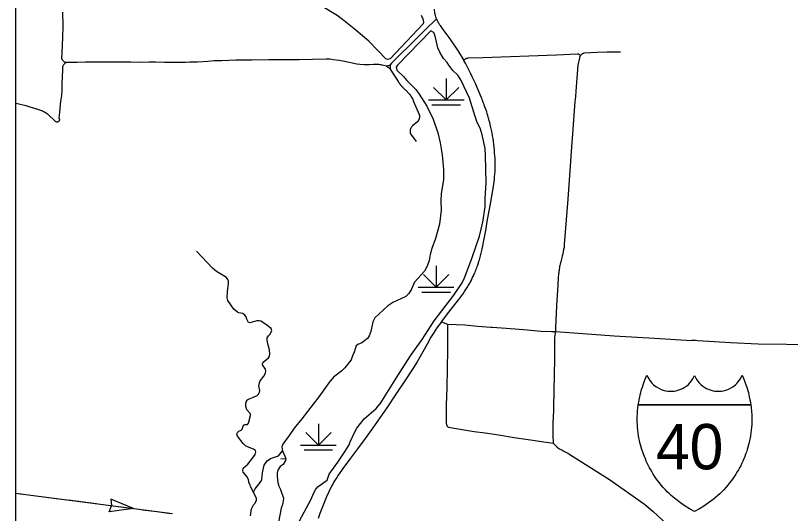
# Model space of a CAD drawing. Extents: x 1127717 to 1741049, y 2026793 to 2244711.
# Drawn here: x 1278363 to 1289221, y 2084628 to 2091610 of the extents above; entities that cross this region are included whole.
import ezdxf

# ---------------------------------------------------------------- set-up
doc = ezdxf.new("R2010")
doc.units = 0
for name, color, linetype in [('1', 7, 'Continuous'), ('23', 7, 'Continuous'), ('31', 7, 'Continuous'), ('32', 7, 'Continuous'), ('35', 7, 'Continuous'), ('43', 7, 'Continuous'), ('44', 7, 'Continuous'), ('45', 7, 'Continuous'), ('47', 7, 'Continuous')]:
    doc.layers.add(name, color=color, linetype=linetype)

msp = doc.modelspace()

# ---------------------------------------------------------------- linework, layer by layer
at = {"layer": '1'}
msp.add_lwpolyline([(1349634, 2111942), (1278363, 2111942), (1278363, 2066677), (1349634, 2066677)], close=True, dxfattribs=at)
at = {"layer": '23'}
for points in [[(1287088, 2086152), (1287094, 2086189), (1287100, 2086223), (1287109, 2086266), (1287115, 2086294), (1287123, 2086327), (1287134, 2086366), (1287145, 2086399), (1287156, 2086432), (1287171, 2086474), (1287186, 2086512), (1287199, 2086543), (1287210, 2086566), (1287222, 2086541), (1287235, 2086516), (1287250, 2086494), (1287269, 2086469), (1287284, 2086452), (1287303, 2086434), (1287322, 2086418), (1287342, 2086403), (1287375, 2086384), (1287409, 2086368), (1287439, 2086357), (1287469, 2086350), (1287501, 2086344), (1287539, 2086342), (1287563, 2086342), (1287591, 2086345), (1287617, 2086349), (1287644, 2086356), (1287671, 2086365), (1287707, 2086381), (1287732, 2086395), (1287762, 2086415), (1287790, 2086439), (1287810, 2086459), (1287833, 2086488), (1287853, 2086516), (1287864, 2086537), (1287876, 2086563)], [(1287876, 2086563), (1287889, 2086537), (1287900, 2086516), (1287920, 2086488), (1287943, 2086459), (1287963, 2086439), (1287991, 2086415), (1288021, 2086395), (1288046, 2086381), (1288082, 2086365), (1288109, 2086356), (1288136, 2086349), (1288161, 2086345), (1288190, 2086342), (1288214, 2086342), (1288252, 2086344), (1288284, 2086350), (1288314, 2086357), (1288344, 2086368), (1288378, 2086384), (1288411, 2086403), (1288431, 2086418), (1288450, 2086434), (1288469, 2086452), (1288484, 2086469), (1288503, 2086494), (1288518, 2086516), (1288531, 2086541), (1288543, 2086566), (1288554, 2086543), (1288567, 2086512), (1288582, 2086474), (1288597, 2086432), (1288608, 2086399), (1288619, 2086366), (1288630, 2086327), (1288638, 2086294), (1288644, 2086266), (1288653, 2086223), (1288659, 2086189), (1288665, 2086152)], [(1287876, 2084658), (1287807, 2084695), (1287747, 2084731), (1287680, 2084776), (1287617, 2084824), (1287549, 2084882), (1287524, 2084906), (1287495, 2084934), (1287468, 2084962), (1287438, 2084994), (1287410, 2085027), (1287385, 2085057), (1287359, 2085091), (1287336, 2085124), (1287315, 2085154), (1287297, 2085182), (1287282, 2085206), (1287262, 2085240), (1287247, 2085267), (1287230, 2085299), (1287214, 2085333), (1287200, 2085363), (1287187, 2085393), (1287173, 2085427), (1287161, 2085458), (1287150, 2085490), (1287139, 2085524), (1287128, 2085558), (1287119, 2085591), (1287112, 2085623), (1287105, 2085650), (1287101, 2085671), (1287093, 2085711), (1287086, 2085758), (1287081, 2085796), (1287078, 2085837), (1287076, 2085870), (1287074, 2085912), (1287074, 2085951), (1287074, 2085994), (1287076, 2086023), (1287077, 2086049), (1287078, 2086065), (1287083, 2086108), (1287088, 2086152)], [(1288665, 2086152), (1287088, 2086152)], [(1287088, 2086152), (1288665, 2086152)], [(1288665, 2086152), (1288670, 2086108), (1288675, 2086065), (1288676, 2086049), (1288677, 2086023), (1288679, 2085994), (1288679, 2085951), (1288679, 2085912), (1288677, 2085870), (1288675, 2085837), (1288672, 2085796), (1288667, 2085758), (1288660, 2085711), (1288652, 2085671), (1288648, 2085650), (1288641, 2085623), (1288634, 2085591), (1288625, 2085558), (1288614, 2085524), (1288603, 2085490), (1288592, 2085458), (1288580, 2085427), (1288566, 2085393), (1288553, 2085363), (1288539, 2085333), (1288523, 2085299), (1288506, 2085267), (1288491, 2085240), (1288471, 2085206), (1288456, 2085182), (1288438, 2085154), (1288417, 2085124), (1288394, 2085091), (1288368, 2085057), (1288343, 2085027), (1288315, 2084994), (1288285, 2084962), (1288258, 2084934), (1288229, 2084906), (1288204, 2084882), (1288136, 2084824), (1288073, 2084776), (1288006, 2084731), (1287946, 2084695), (1287876, 2084658)]]:
    msp.add_lwpolyline(points, dxfattribs=at)
at = {"layer": '31'}
for points in [[(1284263, 2091560), (1284257, 2091576), (1284252, 2091593), (1284247, 2091611), (1284243, 2091628), (1284239, 2091645), (1284236, 2091663), (1284234, 2091681), (1284233, 2091699)], [(1284263, 2091560), (1284250, 2091552), (1284213, 2091519), (1284146, 2091453), (1283929, 2091235), (1283705, 2091016), (1283630, 2090941), (1283613, 2090917)], [(1284263, 2091560), (1284264, 2091557), (1284267, 2091550), (1284268, 2091548), (1284271, 2091541), (1284272, 2091540), (1284275, 2091533), (1284276, 2091531), (1284279, 2091524), (1284280, 2091523), (1284284, 2091516), (1284284, 2091514), (1284288, 2091508), (1284289, 2091506), (1284293, 2091500), (1284294, 2091498), (1284298, 2091492), (1284299, 2091490), (1284303, 2091484), (1284304, 2091482), (1284308, 2091476), (1284309, 2091474), (1284313, 2091468), (1284350, 2091416), (1284432, 2091303), (1284459, 2091268), (1284563, 2091109), (1284644, 2090977)], [(1284929, 2090359), (1284929, 2090361), (1284921, 2090381), (1284921, 2090383), (1284912, 2090405), (1284911, 2090407), (1284903, 2090429), (1284902, 2090431), (1284901, 2090435), (1284900, 2090436), (1284892, 2090457), (1284891, 2090458), (1284833, 2090599), (1284812, 2090647), (1284790, 2090696), (1284767, 2090743), (1284744, 2090791), (1284719, 2090838), (1284695, 2090885), (1284670, 2090931), (1284644, 2090977)], [(1283613, 2090917), (1283605, 2090913), (1283596, 2090909), (1283588, 2090906), (1283579, 2090903), (1283570, 2090900), (1283561, 2090898)], [(1283561, 2090898), (1283571, 2090892), (1283580, 2090886), (1283589, 2090879), (1283598, 2090872), (1283606, 2090865), (1283614, 2090857)], [(1283613, 2090917), (1283611, 2090907), (1283610, 2090897), (1283610, 2090887), (1283611, 2090877), (1283612, 2090867), (1283614, 2090857)], [(1283614, 2090857), (1283724, 2090683), (1283725, 2090681), (1283729, 2090675), (1283730, 2090673), (1283736, 2090665), (1283738, 2090664), (1283743, 2090656), (1283745, 2090654), (1283751, 2090646), (1283752, 2090645), (1283758, 2090637), (1283759, 2090635), (1283766, 2090628), (1283767, 2090626), (1283774, 2090619), (1283775, 2090617), (1283782, 2090610), (1283783, 2090608), (1283790, 2090601), (1283791, 2090600), (1283798, 2090592), (1283799, 2090591), (1283806, 2090584), (1283808, 2090583), (1283815, 2090576), (1283816, 2090574), (1283824, 2090568), (1283825, 2090566), (1283883, 2090506), (1283895, 2090489), (1283906, 2090472), (1283917, 2090454), (1283929, 2090436), (1283941, 2090406), (1284019, 2090222), (1284019, 2090220), (1284020, 2090218), (1284020, 2090216), (1284021, 2090212), (1284021, 2090211), (1284022, 2090207), (1284022, 2090205), (1284022, 2090201), (1284022, 2090199), (1284023, 2090195), (1284023, 2090193), (1284022, 2090189), (1284022, 2090187), (1284022, 2090183), (1284022, 2090181), (1284021, 2090177), (1284021, 2090175), (1284020, 2090172), (1284020, 2090170), (1284019, 2090166), (1284019, 2090164), (1284018, 2090160), (1284017, 2090158), (1284016, 2090155), (1284015, 2090153), (1284013, 2090149), (1284013, 2090147), (1284011, 2090144), (1284010, 2090142), (1284008, 2090139), (1284007, 2090137), (1284005, 2090134), (1284004, 2090132), (1284002, 2090129), (1284001, 2090127), (1283999, 2090126), (1283919, 2090057), (1283914, 2090051), (1283909, 2090044), (1283904, 2090038), (1283901, 2090031), (1283897, 2090023), (1283895, 2090016), (1283893, 2090008), (1283892, 2090000), (1283891, 2089992), (1283891, 2089984), (1283891, 2089976), (1283892, 2089968), (1283894, 2089960), (1283897, 2089953), (1283974, 2089842)], [(1284329, 2087315), (1284434, 2087453), (1284570, 2087626), (1284592, 2087654), (1284613, 2087682), (1284634, 2087710), (1284654, 2087739), (1284673, 2087768), (1284692, 2087798), (1284710, 2087828), (1284727, 2087858), (1284728, 2087860), (1284736, 2087874), (1284737, 2087876), (1284745, 2087891), (1284746, 2087893), (1284754, 2087909), (1284755, 2087911), (1284762, 2087927), (1284763, 2087928), (1284771, 2087944), (1284772, 2087946), (1284779, 2087962), (1284780, 2087964), (1284787, 2087980), (1284788, 2087982), (1284795, 2087998), (1284796, 2088000), (1284803, 2088016), (1284804, 2088018), (1284810, 2088034), (1284811, 2088036), (1284817, 2088053), (1284818, 2088054), (1284824, 2088071), (1284825, 2088073), (1284831, 2088089), (1284832, 2088091), (1284838, 2088108), (1284838, 2088110), (1284844, 2088126), (1284845, 2088128), (1284850, 2088145), (1284851, 2088147), (1284856, 2088164), (1284857, 2088166), (1284862, 2088183), (1284862, 2088185), (1284900, 2088332), (1284933, 2088503), (1284950, 2088597), (1284977, 2088750), (1284982, 2088775), (1285018, 2088971), (1285056, 2089187), (1285072, 2089310), (1285076, 2089347), (1285078, 2089385), (1285081, 2089422), (1285082, 2089460), (1285083, 2089498), (1285083, 2089536), (1285082, 2089573), (1285081, 2089611), (1285079, 2089649), (1285076, 2089686), (1285073, 2089726), (1285070, 2089766), (1285065, 2089805), (1285060, 2089845), (1285054, 2089884), (1285048, 2089924), (1285041, 2089963), (1285033, 2090002), (1285024, 2090041), (1285014, 2090083), (1285013, 2090085), (1285007, 2090108), (1285007, 2090110), (1285001, 2090133), (1285000, 2090135), (1284994, 2090158), (1284993, 2090160), (1284987, 2090182), (1284986, 2090184), (1284980, 2090207), (1284979, 2090209), (1284972, 2090232), (1284972, 2090234), (1284964, 2090256), (1284964, 2090258), (1284956, 2090281), (1284956, 2090282), (1284948, 2090305), (1284948, 2090307), (1284940, 2090329), (1284939, 2090331), (1284931, 2090353), (1284931, 2090355), (1284929, 2090359)], [(1284329, 2087315), (1284298, 2087274), (1284268, 2087230), (1284217, 2087156), (1284183, 2087100), (1284129, 2087003), (1283991, 2086756), (1283936, 2086665), (1283810, 2086475), (1283703, 2086315), (1283565, 2086109), (1283371, 2085829), (1283264, 2085680), (1283154, 2085534), (1283057, 2085404), (1283034, 2085372), (1282974, 2085290), (1282951, 2085260), (1282929, 2085229), (1282907, 2085198), (1282885, 2085166), (1282864, 2085134), (1282843, 2085102), (1282825, 2085072), (1282807, 2085042), (1282791, 2085012), (1282774, 2084981), (1282757, 2084945), (1282741, 2084910), (1282725, 2084874), (1282709, 2084839), (1282681, 2084769), (1282654, 2084700), (1282627, 2084630), (1282601, 2084560)]]:
    msp.add_lwpolyline(points, dxfattribs=at)
at = {"layer": '32'}
for points in [[(1286279, 2091051), (1286265, 2091059), (1286252, 2091067), (1286233, 2091070), (1285944, 2091053), (1284910, 2091015), (1284698, 2091010), (1284693, 2091009), (1284686, 2091008), (1284680, 2091007), (1284674, 2091004), (1284668, 2091001), (1284662, 2090997), (1284657, 2090993), (1284652, 2090988), (1284647, 2090983), (1284644, 2090977)], [(1284329, 2087315), (1284417, 2087283)], [(1284417, 2087283), (1284538, 2087278), (1284656, 2087272), (1284841, 2087257), (1285022, 2087243), (1285043, 2087241), (1285235, 2087226), (1285480, 2087206), (1285726, 2087186), (1285873, 2087178), (1285927, 2087180)]]:
    msp.add_lwpolyline(points, dxfattribs=at)
at = {"layer": '35'}
for points in [[(1281863, 2087283), (1281799, 2087324), (1281776, 2087331), (1281745, 2087331), (1281648, 2087301), (1281625, 2087306), (1281605, 2087353), (1281595, 2087384), (1281578, 2087411), (1281547, 2087431), (1281494, 2087441), (1281475, 2087450), (1281423, 2087495), (1281339, 2087616), (1281328, 2087653), (1281333, 2087734), (1281348, 2087851), (1281345, 2087884), (1281338, 2087907), (1281317, 2087939), (1281177, 2088021), (1281121, 2088070), (1280900, 2088308)], [(1281630, 2085079), (1281626, 2085101), (1281607, 2085141), (1281551, 2085206), (1281546, 2085225), (1281553, 2085263), (1281616, 2085320), (1281671, 2085384), (1281721, 2085455), (1281729, 2085495), (1281723, 2085514), (1281696, 2085531), (1281614, 2085563), (1281584, 2085579), (1281551, 2085609), (1281475, 2085714), (1281466, 2085744), (1281472, 2085763), (1281490, 2085781), (1281525, 2085795), (1281539, 2085812), (1281559, 2085869), (1281576, 2085878), (1281611, 2085874), (1281629, 2085893), (1281655, 2086004), (1281653, 2086028), (1281604, 2086084), (1281589, 2086135), (1281590, 2086175), (1281606, 2086218), (1281627, 2086231), (1281696, 2086259), (1281749, 2086285), (1281767, 2086302), (1281781, 2086328), (1281784, 2086355), (1281773, 2086419), (1281779, 2086462), (1281791, 2086490), (1281842, 2086553), (1281864, 2086594), (1281870, 2086622), (1281865, 2086651), (1281824, 2086712), (1281822, 2086728), (1281831, 2086750), (1281907, 2086810), (1281920, 2086832), (1281926, 2086864), (1281923, 2086924), (1281891, 2087024), (1281887, 2087066), (1281890, 2087089), (1281908, 2087118), (1281927, 2087139), (1281955, 2087189), (1281947, 2087220), (1281863, 2087283)], [(1281696, 2084927), (1281722, 2084973), (1281759, 2085020), (1281805, 2085080), (1281814, 2085106), (1281824, 2085197), (1281846, 2085308), (1281890, 2085369), (1281937, 2085400), (1282048, 2085436), (1282104, 2085507)], [(1281655, 2084597), (1281669, 2084692), (1281698, 2084749), (1281719, 2084775), (1281741, 2084814), (1281738, 2084839), (1281718, 2084891), (1281657, 2085007), (1281652, 2085026), (1281631, 2085068), (1281630, 2085079)]]:
    msp.add_lwpolyline(points, dxfattribs=at)
at = {"layer": '43'}
for p, q in [((1280015, 2084699), (1279698, 2084830)), ((1279698, 2084830), (1279710, 2084739)), ((1279675, 2084653), (1279710, 2084738)), ((1280015, 2084699), (1279675, 2084653))]:
    msp.add_line(p, q, dxfattribs=at)
for points in [[(1278363, 2084915), (1280564, 2084627)], [(1278363, 2084915), (1278445, 2084904)], [(1278576, 2084887), (1278968, 2084836)], [(1279099, 2084818), (1279492, 2084767)], [(1279623, 2084750), (1280015, 2084699)], [(1280146, 2084681), (1280343, 2084656)], [(1280343, 2084656), (1280539, 2084630)]]:
    msp.add_lwpolyline(points, dxfattribs=at)
at = {"layer": '44'}
for p, q in [((1284397, 2090726), (1284397, 2090426)), ((1284397, 2090426), (1284220, 2090602)), ((1284397, 2090426), (1284573, 2090602)), ((1284147, 2090426), (1284647, 2090426)), ((1284197, 2090357), (1284597, 2090357)), ((1284256, 2088101), (1284256, 2087801)), ((1284256, 2087801), (1284079, 2087978)), ((1284256, 2087801), (1284433, 2087978)), ((1284006, 2087801), (1284506, 2087801)), ((1284056, 2087733), (1284456, 2087733)), ((1282606, 2085887), (1282606, 2085587)), ((1282606, 2085587), (1282429, 2085763)), ((1282606, 2085587), (1282783, 2085763)), ((1282356, 2085587), (1282856, 2085587)), ((1282406, 2085519), (1282806, 2085519))]:
    msp.add_line(p, q, dxfattribs=at)
at = {"layer": '45'}
for points in [[(1279074, 2090950), (1279061, 2090953), (1279055, 2090955), (1279050, 2090957), (1279044, 2090960), (1279039, 2090964), (1279034, 2090968), (1279030, 2090972), (1279026, 2090977), (1279023, 2090982), (1279020, 2090988), (1279017, 2090993), (1279015, 2090999), (1279014, 2091005), (1279018, 2091090), (1279023, 2091188), (1279028, 2091309), (1279032, 2091451), (1279031, 2091526), (1279028, 2091593), (1279026, 2091655)], [(1286841, 2091094), (1286784, 2091097), (1286652, 2091098), (1286511, 2091093), (1286331, 2091082), (1286325, 2091081), (1286319, 2091079), (1286313, 2091077), (1286307, 2091074), (1286302, 2091071), (1286297, 2091067), (1286292, 2091063), (1286287, 2091059), (1286283, 2091055), (1286279, 2091050), (1286275, 2091046), (1286272, 2091040), (1286269, 2091035), (1286267, 2091030), (1286265, 2091024), (1286263, 2091018), (1286240, 2090912), (1286213, 2090551), (1286207, 2090474), (1286204, 2090431), (1286201, 2090405), (1286162, 2089886), (1286158, 2089836)], [(1279074, 2090950), (1279067, 2090947), (1279060, 2090944), (1279054, 2090939), (1279048, 2090934), (1279043, 2090929), (1279038, 2090923), (1279034, 2090917), (1279030, 2090911), (1279027, 2090904), (1279025, 2090897), (1279023, 2090890), (1279022, 2090882), (1279021, 2090875), (1279021, 2090867), (1279015, 2090728), (1279014, 2090674), (1279011, 2090570), (1279005, 2090485), (1278994, 2090410), (1278978, 2090257), (1278977, 2090250), (1278972, 2090176), (1278972, 2090170), (1278973, 2090164), (1278974, 2090158), (1278977, 2090152), (1278980, 2090147), (1278984, 2090141)], [(1283561, 2090898), (1283500, 2090914), (1283485, 2090918), (1283470, 2090920), (1283455, 2090922), (1283440, 2090923), (1283425, 2090924), (1283409, 2090924), (1283380, 2090922), (1283318, 2090920), (1283254, 2090918), (1283186, 2090924), (1283147, 2090930), (1282972, 2090966), (1282899, 2090980), (1282815, 2090991), (1282770, 2090997), (1282715, 2090999), (1282526, 2090995), (1282335, 2090988), (1282101, 2090987), (1281914, 2090988), (1281673, 2090986), (1281448, 2090982), (1281253, 2090976), (1281145, 2090974), (1281058, 2090965), (1280913, 2090957), (1280804, 2090955), (1280745, 2090953), (1280697, 2090953), (1280585, 2090953), (1280448, 2090952), (1280324, 2090954), (1280232, 2090956), (1280114, 2090953), (1279977, 2090955), (1279909, 2090956), (1279763, 2090956), (1279524, 2090955), (1279345, 2090954), (1279228, 2090953), (1279074, 2090950)], [(1278363, 2090382), (1278391, 2090375), (1278506, 2090349), (1278549, 2090336), (1278683, 2090293), (1278698, 2090289), (1278713, 2090284), (1278727, 2090278), (1278742, 2090272), (1278756, 2090265), (1278770, 2090258), (1278781, 2090251), (1278783, 2090250), (1278797, 2090242), (1278809, 2090233), (1278822, 2090224), (1278914, 2090134), (1278918, 2090129), (1278922, 2090126), (1278926, 2090123), (1278931, 2090120), (1278936, 2090119), (1278941, 2090118), (1278946, 2090118), (1278952, 2090118), (1278957, 2090120), (1278961, 2090122), (1278984, 2090141)], [(1286158, 2089836), (1286135, 2089499), (1286102, 2089036), (1286065, 2088572), (1286052, 2088401), (1286051, 2088395)], [(1286051, 2088395), (1286048, 2088356), (1286042, 2088328), (1286036, 2088299), (1286030, 2088270), (1286024, 2088242), (1286018, 2088213), (1286001, 2088156), (1286000, 2088154), (1285997, 2088141), (1285997, 2088139), (1285993, 2088124), (1285993, 2088122), (1285990, 2088107), (1285989, 2088105), (1285986, 2088090), (1285986, 2088088), (1285983, 2088073), (1285983, 2088071), (1285981, 2088056), (1285980, 2088054), (1285978, 2088039), (1285978, 2088037), (1285976, 2088021), (1285975, 2088020), (1285973, 2088004), (1285973, 2088002), (1285972, 2087987), (1285971, 2087985), (1285970, 2087970), (1285970, 2087968), (1285968, 2087953), (1285968, 2087951), (1285967, 2087937), (1285961, 2087828), (1285944, 2087543), (1285930, 2087232), (1285927, 2087180)], [(1284417, 2087283), (1284415, 2087222), (1284417, 2087060), (1284415, 2086929), (1284410, 2086663), (1284404, 2086388), (1284398, 2086152), (1284396, 2085901), (1284396, 2085900), (1284397, 2085896), (1284397, 2085895), (1284398, 2085889), (1284398, 2085888), (1284399, 2085883), (1284399, 2085882), (1284400, 2085877), (1284401, 2085876), (1284402, 2085871), (1284402, 2085870), (1284404, 2085865), (1284404, 2085864), (1284406, 2085860), (1284407, 2085859), (1284408, 2085856), (1284414, 2085850), (1284421, 2085845), (1284428, 2085841), (1284435, 2085838), (1284507, 2085823), (1284648, 2085801), (1284789, 2085779), (1284941, 2085759), (1285067, 2085740), (1285130, 2085730), (1285347, 2085695), (1285609, 2085655), (1285796, 2085628), (1285894, 2085615)], [(1285927, 2087180), (1285923, 2087160), (1285920, 2087126), (1285916, 2087095), (1285912, 2086802), (1285908, 2086569), (1285905, 2086351), (1285901, 2086115), (1285894, 2085943), (1285894, 2085941), (1285893, 2085926), (1285893, 2085924), (1285892, 2085906), (1285892, 2085904), (1285891, 2085887), (1285891, 2085885), (1285891, 2085868), (1285891, 2085866), (1285891, 2085848), (1285890, 2085846), (1285891, 2085837), (1285892, 2085725), (1285894, 2085615)], [(1285927, 2087180), (1286060, 2087171), (1286749, 2087120), (1287314, 2087085), (1287835, 2087056)], [(1287923, 2087051), (1287888, 2087053), (1287835, 2087056)], [(1289392, 2086995), (1289165, 2086998), (1288769, 2087004), (1288378, 2087023), (1287923, 2087051)], [(1285894, 2085615), (1285909, 2085600), (1285924, 2085586), (1285939, 2085571), (1285953, 2085556), (1285954, 2085555), (1285956, 2085553), (1285957, 2085553), (1285960, 2085550), (1285960, 2085550), (1285964, 2085547), (1285965, 2085547), (1285968, 2085544), (1285969, 2085544), (1285972, 2085542), (1285973, 2085541), (1285977, 2085539), (1285978, 2085539), (1285981, 2085537), (1285982, 2085537), (1285984, 2085536), (1285986, 2085535), (1286014, 2085520), (1286015, 2085519), (1286043, 2085504), (1286045, 2085503), (1286072, 2085488), (1286074, 2085487), (1286101, 2085472), (1286103, 2085471), (1286113, 2085465), (1286114, 2085465), (1286166, 2085432), (1286686, 2085103), (1287173, 2084761), (1287295, 2084657), (1287552, 2084419)]]:
    msp.add_lwpolyline(points, dxfattribs=at)
at = {"layer": '47'}
for points in [[(1284045, 2091614), (1284071, 2091564), (1284078, 2091516), (1284075, 2091492), (1283612, 2091003), (1283576, 2090994), (1283552, 2091004), (1283440, 2091118), (1283313, 2091252), (1283106, 2091424), (1282946, 2091555), (1282871, 2091610), (1282397, 2091901)], [(1284812, 2088367), (1284864, 2088516), (1284911, 2088713), (1284945, 2088926), (1284943, 2089043), (1284956, 2089262), (1284949, 2089649), (1284941, 2089745), (1284900, 2089939), (1284872, 2090033), (1284833, 2090112), (1284802, 2090194), (1284723, 2090453), (1284603, 2090710), (1284559, 2090774), (1284492, 2090841), (1284435, 2090912), (1284410, 2090952), (1284359, 2091009), (1284306, 2091094), (1284279, 2091156), (1284246, 2091300), (1284227, 2091362), (1284213, 2091378), (1284182, 2091393), (1283716, 2090916), (1283694, 2090884), (1283707, 2090842), (1283801, 2090755), (1283846, 2090700), (1283970, 2090573), (1284019, 2090508), (1284126, 2090337), (1284215, 2090158), (1284279, 2089965), (1284311, 2089827), (1284342, 2089655), (1284361, 2089452), (1284358, 2089310), (1284327, 2089111), (1284323, 2089018), (1284325, 2088880), (1284302, 2088685), (1284248, 2088482), (1284198, 2088344), (1284173, 2088258), (1284157, 2088175), (1284130, 2088098), (1284093, 2088028), (1283953, 2087871), (1283909, 2087774), (1283872, 2087711), (1283831, 2087670), (1283648, 2087587), (1283580, 2087538), (1283399, 2087372), (1283370, 2087317), (1283340, 2087179), (1283317, 2087120), (1283294, 2087083), (1283215, 2087020), (1283159, 2086999), (1283137, 2086981), (1283120, 2086938), (1283109, 2086888), (1283085, 2086837)], [(1282341, 2084526), (1282504, 2084830), (1282539, 2084910), (1282572, 2084971), (1282601, 2085008), (1282730, 2085094), (1282755, 2085181), (1282878, 2085349), (1282980, 2085501), (1283036, 2085589), (1283050, 2085633), (1283111, 2085764), (1283147, 2085823), (1283250, 2085955), (1283414, 2086102), (1283479, 2086178), (1283544, 2086279), (1283731, 2086577), (1283908, 2086851), (1284059, 2087066), (1284227, 2087330), (1284505, 2087691), (1284619, 2087860), (1284655, 2087933), (1284757, 2088205), (1284812, 2088367)], [(1283085, 2086837), (1283064, 2086785), (1282978, 2086671), (1282937, 2086628), (1282820, 2086542), (1282753, 2086461), (1282612, 2086266), (1282373, 2085957), (1282269, 2085827), (1282199, 2085721), (1282109, 2085601), (1282096, 2085561), (1282104, 2085507), (1282150, 2085401)], [(1282082, 2085394), (1282150, 2085401), (1282147, 2085371), (1282113, 2085317), (1282072, 2085288), (1282037, 2085235), (1282027, 2085197), (1282028, 2085145), (1282038, 2085064), (1282054, 2085013), (1282077, 2084965), (1282119, 2084845), (1282107, 2084767), (1282086, 2084702), (1282007, 2084288)]]:
    msp.add_lwpolyline(points, dxfattribs=at)

# ---------------------------------------------------------------- texts
at = {"layer": '23'}
msp.add_text('40', height=635.2, dxfattribs=at).set_placement((1287335, 2085248))

doc.saveas('drawing.dxf')
